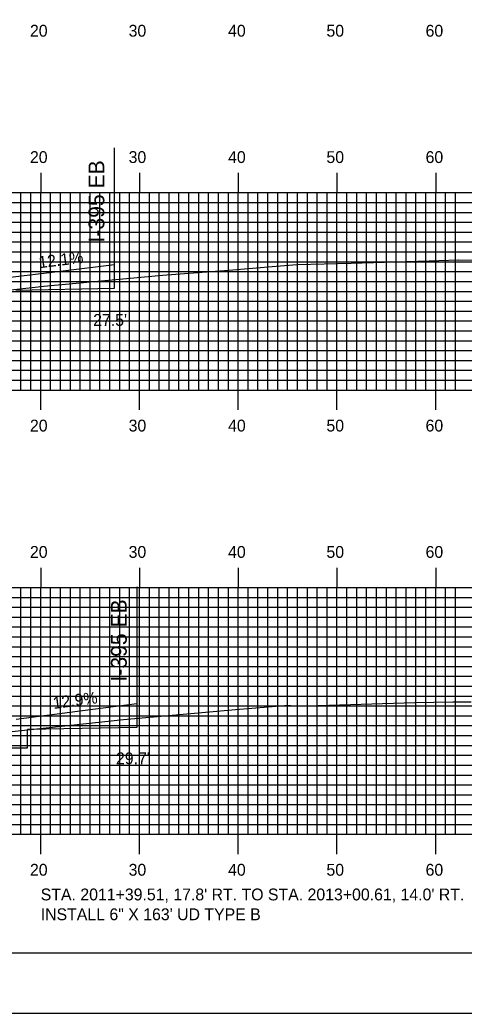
# Model space of a CAD drawing. Extents: x 853894 to 854237, y 366605 to 366825.
# Drawn here: x 854077.4 to 854122.4, y 366604.9 to 366705.6 of the extents above; entities that cross this region are included whole.
import ezdxf

# ---------------------------------------------------------------- set-up
doc = ezdxf.new("R2010")
doc.units = 0
for name, color, linetype in [('ANNOTATION', 7, 'Continuous'), ('BORDER', 7, 'Continuous'), ('D_Roadway_Centerline', 7, 'Continuous'), ('D_Roadway_SubGrade', 7, 'Continuous'), ('D_Text_Standard', 7, 'Continuous'), ('H_V ANNOTATION', 7, 'Continuous'), ('M_Roadway_Centerline', 7, 'Continuous'), ('MAJOR', 7, 'Continuous'), ('MINOR', 7, 'Continuous'), ('PDRAIN', 7, 'Continuous'), ('PLOT BOUNDARY', 7, 'Continuous'), ('S_Roadway_Centerline', 7, 'Continuous')]:
    doc.layers.add(name, color=color, linetype=linetype)

msp = doc.modelspace()

# ---------------------------------------------------------------- linework, layer by layer
at = {"layer": 'BORDER'}
msp.add_lwpolyline([(853909.93, 366611.06), (854229.93, 366611.06), (854229.93, 366821.06), (853909.93, 366821.06)], close=True, dxfattribs=at)
at = {"layer": 'D_Roadway_Centerline'}
for p, q in [((854086.98, 366678.36), (854077, 366678.16)), ((854089.26, 366633.89), (854078.18, 366633.66))]:
    msp.add_line(p, q, dxfattribs=at)
for points in [[(854075.88, 366679.43), (854081.53, 366680.12), (854086.98, 366680.78)], [(854077.06, 366634.73), (854084.02, 366635.63), (854089.26, 366636.31)]]:
    msp.add_lwpolyline(points, dxfattribs=at)
at = {"layer": 'D_Roadway_SubGrade'}
for p, q in [((854086.98, 366692.59), (854086.98, 366678.36)), ((854089.26, 366648.11), (854089.26, 366633.89))]:
    msp.add_line(p, q, dxfattribs=at)
at = {"layer": 'MAJOR'}
for p, q in [((854079.53, 366690.06), (854079.53, 366688.06)), ((854089.53, 366690.06), (854089.53, 366688.06)), ((854099.53, 366690.06), (854099.53, 366688.06)), ((854109.53, 366690.06), (854109.53, 366688.06)), ((854119.53, 366690.06), (854119.53, 366688.06)), ((853919.53, 366688.06), (854199.53, 366688.06)), ((853919.53, 366688.06), (854199.53, 366688.06)), ((854079.53, 366668.06), (854079.53, 366688.06)), ((854089.53, 366668.06), (854089.53, 366688.06)), ((854099.53, 366668.06), (854099.53, 366688.06)), ((854109.53, 366668.06), (854109.53, 366688.06)), ((854119.53, 366668.06), (854119.53, 366688.06)), ((853919.53, 366683.06), (854199.53, 366683.06)), ((853919.53, 366678.06), (854199.53, 366678.06)), ((853919.53, 366673.06), (854199.53, 366673.06)), ((853919.53, 366668.06), (854199.53, 366668.06)), ((853919.53, 366668.06), (854199.53, 366668.06)), ((854079.53, 366666.05), (854079.53, 366668.06)), ((854089.53, 366666.05), (854089.53, 366668.06)), ((854099.53, 366666.05), (854099.53, 366668.06)), ((854109.53, 366666.05), (854109.53, 366668.06)), ((854119.53, 366666.05), (854119.53, 366668.06)), ((854079.53, 366650.06), (854079.53, 366648.06)), ((854089.53, 366650.06), (854089.53, 366648.06)), ((854099.53, 366650.06), (854099.53, 366648.06)), ((854109.53, 366650.06), (854109.53, 366648.06)), ((854119.53, 366650.06), (854119.53, 366648.06)), ((853919.53, 366648.06), (854199.53, 366648.06)), ((853919.53, 366648.06), (854199.53, 366648.06)), ((854079.53, 366623.06), (854079.53, 366648.06)), ((854089.53, 366623.06), (854089.53, 366648.06)), ((854099.53, 366623.06), (854099.53, 366648.06)), ((854109.53, 366623.06), (854109.53, 366648.06)), ((854119.53, 366623.06), (854119.53, 366648.06)), ((853919.53, 366643.06), (854199.53, 366643.06)), ((853919.53, 366638.06), (854199.53, 366638.06)), ((853919.53, 366633.06), (854199.53, 366633.06)), ((853919.53, 366628.06), (854199.53, 366628.06)), ((853919.53, 366623.06), (854199.53, 366623.06)), ((853919.53, 366623.06), (854199.53, 366623.06)), ((854079.53, 366621.05), (854079.53, 366623.06)), ((854089.53, 366621.05), (854089.53, 366623.06)), ((854099.53, 366621.05), (854099.53, 366623.06)), ((854109.53, 366621.05), (854109.53, 366623.06)), ((854119.53, 366621.05), (854119.53, 366623.06))]:
    msp.add_line(p, q, dxfattribs=at)
at = {"layer": 'MINOR'}
for p, q in [((854077.53, 366668.06), (854077.53, 366688.06)), ((854078.53, 366668.06), (854078.53, 366688.06)), ((854080.53, 366668.06), (854080.53, 366688.06)), ((854081.53, 366668.06), (854081.53, 366688.06)), ((854082.53, 366668.06), (854082.53, 366688.06)), ((854083.53, 366668.06), (854083.53, 366688.06)), ((854084.53, 366668.06), (854084.53, 366688.06)), ((854085.53, 366668.06), (854085.53, 366688.06)), ((854086.53, 366668.06), (854086.53, 366688.06)), ((854087.53, 366668.06), (854087.53, 366688.06)), ((854088.53, 366668.06), (854088.53, 366688.06)), ((854090.53, 366668.06), (854090.53, 366688.06)), ((854091.53, 366668.06), (854091.53, 366688.06)), ((854092.53, 366668.06), (854092.53, 366688.06)), ((854093.53, 366668.06), (854093.53, 366688.06)), ((854094.53, 366668.06), (854094.53, 366688.06)), ((854095.53, 366668.06), (854095.53, 366688.06)), ((854096.53, 366668.06), (854096.53, 366688.06)), ((854097.53, 366668.06), (854097.53, 366688.06)), ((854098.53, 366668.06), (854098.53, 366688.06)), ((854100.53, 366668.06), (854100.53, 366688.06)), ((854101.53, 366668.06), (854101.53, 366688.06)), ((854102.53, 366668.06), (854102.53, 366688.06)), ((854103.53, 366668.06), (854103.53, 366688.06)), ((854104.53, 366668.06), (854104.53, 366688.06)), ((854105.53, 366668.06), (854105.53, 366688.06)), ((854106.53, 366668.06), (854106.53, 366688.06)), ((854107.53, 366668.06), (854107.53, 366688.06)), ((854108.53, 366668.06), (854108.53, 366688.06)), ((854110.53, 366668.06), (854110.53, 366688.06)), ((854111.53, 366668.06), (854111.53, 366688.06)), ((854112.53, 366668.06), (854112.53, 366688.06)), ((854113.53, 366668.06), (854113.53, 366688.06)), ((854114.53, 366668.06), (854114.53, 366688.06)), ((854115.53, 366668.06), (854115.53, 366688.06)), ((854116.53, 366668.06), (854116.53, 366688.06)), ((854117.53, 366668.06), (854117.53, 366688.06)), ((854118.53, 366668.06), (854118.53, 366688.06)), ((854120.53, 366668.06), (854120.53, 366688.06)), ((854121.53, 366668.06), (854121.53, 366688.06)), ((853919.53, 366687.06), (854199.53, 366687.06)), ((853919.53, 366686.06), (854199.53, 366686.06)), ((853919.53, 366685.06), (854199.53, 366685.06)), ((853919.53, 366684.06), (854199.53, 366684.06)), ((853919.53, 366682.06), (854199.53, 366682.06)), ((853919.53, 366681.06), (854199.53, 366681.06)), ((853919.53, 366680.06), (854199.53, 366680.06)), ((853919.53, 366679.06), (854199.53, 366679.06)), ((853919.53, 366677.06), (854199.53, 366677.06)), ((853919.53, 366676.06), (854199.53, 366676.06)), ((853919.53, 366675.06), (854199.53, 366675.06)), ((853919.53, 366674.06), (854199.53, 366674.06)), ((853919.53, 366672.06), (854199.53, 366672.06)), ((853919.53, 366671.06), (854199.53, 366671.06)), ((853919.53, 366670.06), (854199.53, 366670.06)), ((853919.53, 366669.06), (854199.53, 366669.06)), ((854077.53, 366623.06), (854077.53, 366648.06)), ((854078.53, 366623.06), (854078.53, 366648.06)), ((854080.53, 366623.06), (854080.53, 366648.06)), ((854081.53, 366623.06), (854081.53, 366648.06)), ((854082.53, 366623.06), (854082.53, 366648.06)), ((854083.53, 366623.06), (854083.53, 366648.06)), ((854084.53, 366623.06), (854084.53, 366648.06)), ((854085.53, 366623.06), (854085.53, 366648.06)), ((854086.53, 366623.06), (854086.53, 366648.06)), ((854087.53, 366623.06), (854087.53, 366648.06)), ((854088.53, 366623.06), (854088.53, 366648.06)), ((854090.53, 366623.06), (854090.53, 366648.06)), ((854091.53, 366623.06), (854091.53, 366648.06)), ((854092.53, 366623.06), (854092.53, 366648.06)), ((854093.53, 366623.06), (854093.53, 366648.06)), ((854094.53, 366623.06), (854094.53, 366648.06)), ((854095.53, 366623.06), (854095.53, 366648.06)), ((854096.53, 366623.06), (854096.53, 366648.06)), ((854097.53, 366623.06), (854097.53, 366648.06)), ((854098.53, 366623.06), (854098.53, 366648.06)), ((854100.53, 366623.06), (854100.53, 366648.06)), ((854101.53, 366623.06), (854101.53, 366648.06)), ((854102.53, 366623.06), (854102.53, 366648.06)), ((854103.53, 366623.06), (854103.53, 366648.06)), ((854104.53, 366623.06), (854104.53, 366648.06)), ((854105.53, 366623.06), (854105.53, 366648.06)), ((854106.53, 366623.06), (854106.53, 366648.06)), ((854107.53, 366623.06), (854107.53, 366648.06)), ((854108.53, 366623.06), (854108.53, 366648.06)), ((854110.53, 366623.06), (854110.53, 366648.06)), ((854111.53, 366623.06), (854111.53, 366648.06)), ((854112.53, 366623.06), (854112.53, 366648.06)), ((854113.53, 366623.06), (854113.53, 366648.06)), ((854114.53, 366623.06), (854114.53, 366648.06)), ((854115.53, 366623.06), (854115.53, 366648.06)), ((854116.53, 366623.06), (854116.53, 366648.06)), ((854117.53, 366623.06), (854117.53, 366648.06)), ((854118.53, 366623.06), (854118.53, 366648.06)), ((854120.53, 366623.06), (854120.53, 366648.06)), ((854121.53, 366623.06), (854121.53, 366648.06)), ((853919.53, 366647.06), (854199.53, 366647.06)), ((853919.53, 366646.06), (854199.53, 366646.06)), ((853919.53, 366645.06), (854199.53, 366645.06)), ((853919.53, 366644.06), (854199.53, 366644.06)), ((853919.53, 366642.06), (854199.53, 366642.06)), ((853919.53, 366641.06), (854199.53, 366641.06)), ((853919.53, 366640.06), (854199.53, 366640.06)), ((853919.53, 366639.06), (854199.53, 366639.06)), ((853919.53, 366637.06), (854199.53, 366637.06)), ((853919.53, 366636.06), (854199.53, 366636.06)), ((853919.53, 366635.06), (854199.53, 366635.06)), ((853919.53, 366634.06), (854199.53, 366634.06)), ((853919.53, 366632.06), (854199.53, 366632.06)), ((853919.53, 366631.06), (854199.53, 366631.06)), ((853919.53, 366630.06), (854199.53, 366630.06)), ((853919.53, 366629.06), (854199.53, 366629.06)), ((853919.53, 366627.06), (854199.53, 366627.06)), ((853919.53, 366626.06), (854199.53, 366626.06)), ((853919.53, 366625.06), (854199.53, 366625.06)), ((853919.53, 366624.06), (854199.53, 366624.06))]:
    msp.add_line(p, q, dxfattribs=at)
at = {"layer": 'PDRAIN'}
msp.add_lwpolyline([(854075.93, 366633.1), (854075.93, 366631.81), (854078.18, 366631.81), (854078.18, 366633.66)], dxfattribs=at)
at = {"layer": 'PLOT BOUNDARY'}
msp.add_lwpolyline([(853893.74, 366604.94), (854233.74, 366604.94), (854233.74, 366824.94), (853893.74, 366824.94)], close=True, dxfattribs=at)
at = {"layer": 'S_Roadway_Centerline'}
for points in [[(854064.08, 366676.85), (854079.27, 366678.53), (854079.44, 366678.54), (854079.59, 366678.56), (854079.86, 366678.59), (854091.85, 366679.71), (854098.58, 366680.22), (854103.37, 366680.62), (854105.51, 366680.77), (854110.97, 366680.92), (854117.73, 366681.1), (854117.85, 366681.1), (854121.85, 366681.24), (854121.87, 366681.24), (854124.81, 366681.19)], [(854070.02, 366632.77), (854087.92, 366634.69), (854099.26, 366635.69), (854104.2, 366636.11), (854104.87, 366636.1), (854105.67, 366636.07), (854107.62, 366636.1), (854117.42, 366636.42), (854121.26, 366636.48), (854123.11, 366636.48)]]:
    msp.add_lwpolyline(points, dxfattribs=at)

# ---------------------------------------------------------------- texts
at = {"layer": 'ANNOTATION'}
for s, height, rotation, p in [('I-395 EB', 1.6, 90, (854085.97, 366683.01)), ('12.1%', 1.2, 6.9247, (854079.38, 366680.4)), ('I-395 EB', 1.6, 90, (854088.24, 366638.53)), ('12.9%', 1.2, 7.3685, (854080.83, 366635.75))]:
    msp.add_text(s, height=height, rotation=rotation, dxfattribs=at).set_placement(p)
for s, p in [("STA. 2011+39.51, 17.8' RT. TO STA. 2013+00.61, 14.0' RT.", (854079.53, 366616.36)), ('INSTALL 6" X 163\' UD TYPE B', (854079.53, 366614.35))]:
    msp.add_text(s, height=1.2, dxfattribs=at).set_placement(p)
at = {"layer": 'D_Text_Standard'}
for s, p in [("27.5'", (854084.84, 366674.56)), ("29.7'", (854087.15, 366630.15))]:
    msp.add_text(s, height=1.2, dxfattribs=at).set_placement(p)
at = {"layer": 'H_V ANNOTATION'}
for s, p in [('20', (854078.44, 366703.86)), ('30', (854088.43, 366703.86)), ('40', (854098.5, 366703.86)), ('50', (854108.46, 366703.86)), ('60', (854118.5, 366703.86)), ('20', (854078.44, 366691.06)), ('30', (854088.43, 366691.06)), ('40', (854098.5, 366691.06)), ('50', (854108.46, 366691.06)), ('60', (854118.5, 366691.06)), ('20', (854078.44, 366663.86)), ('30', (854088.43, 366663.86)), ('40', (854098.5, 366663.86)), ('50', (854108.46, 366663.86)), ('60', (854118.5, 366663.86)), ('20', (854078.44, 366651.06)), ('30', (854088.43, 366651.06)), ('40', (854098.5, 366651.06)), ('50', (854108.46, 366651.06)), ('60', (854118.5, 366651.06)), ('20', (854078.44, 366618.86)), ('30', (854088.43, 366618.86)), ('40', (854098.5, 366618.86)), ('50', (854108.46, 366618.86)), ('60', (854118.5, 366618.86))]:
    msp.add_text(s, height=1.2, dxfattribs=at).set_placement(p)
at = {"layer": 'M_Roadway_Centerline'}
for s, p in [('C', (854121.85, 366681.24)), ('L', (854121.85, 366681.23))]:
    msp.add_text(s, height=0.0146, dxfattribs=at).set_placement(p)

doc.saveas('drawing.dxf')
